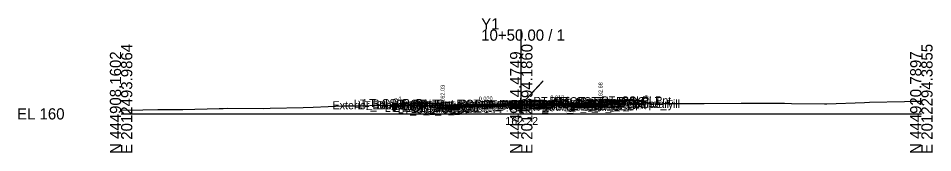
# Model space of a CAD drawing. Extents: x -26 to 3203, y -10 to 9517.
# Drawn here: x -25.7 to 202.8, y 990.3 to 1023.9 of the extents above; entities that cross this region are included whole.
import ezdxf

# ---------------------------------------------------------------- set-up
doc = ezdxf.new("R2010")
doc.units = 0
for name, color, linetype in [('Default', 7, 'Continuous'), ('Exist CMT Pavement', 7, 'Continuous'), ('Exist Cross Section Cell', 7, 'Continuous'), ('Exist XS Center Line Elevation Label', 7, 'Continuous'), ('Exist XS Ground Line', 7, 'Continuous'), ('Prop CMT Conc Surface', 7, 'Continuous'), ('Prop CMT Concrete Structures', 7, 'Continuous'), ('Prop CMT Pvmt Course 1', 7, 'Continuous'), ('Prop CMT Pvmt Course 1 CG', 7, 'Continuous'), ('Prop CMT Pvmt Course 1 Wedge', 7, 'Continuous'), ('Prop CMT Pvmt Course 2', 7, 'Continuous'), ('Prop CMT Pvmt Course 2 Wedge', 7, 'Continuous'), ('Prop CMT Pvmt Course 3', 7, 'Continuous'), ('Prop CMT Pvmt Course 3 Wedge', 7, 'Continuous'), ('Prop CMT Pvmt Surface', 7, 'Continuous'), ('Prop CMT Pvmt Wedge Surface 1', 7, 'Continuous'), ('Prop CMT Pvmt Wedge Surface 2', 7, 'Continuous'), ('Prop CMT Pvmt Wedge Surface 3', 7, 'Continuous'), ('Prop CMT Slope Grass', 7, 'Continuous'), ('Prop CMT Subgrade Earthwork', 7, 'Continuous'), ('Prop XS Earthwork Shape', 7, 'Continuous'), ('Prop XS Hydro Elevations', 7, 'Continuous'), ('Prop XS SE Text', 7, 'Continuous'), ('Prop XS Side Slope Text', 7, 'Continuous'), ('Prop XS Wedging', 7, 'Continuous'), ('Scratch_Level_0', 7, 'Continuous')]:
    doc.layers.add(name, color=color, linetype=linetype)

msp = doc.modelspace()

# ---------------------------------------------------------------- linework, layer by layer
at = {"layer": 'Exist CMT Pavement'}
for points in [[(100, 1002.22), (98.21, 1002.22), (86.33, 1001.92), (84.56, 1002.08)], [(100, 1002.22), (110.58, 1002.2), (112.49, 1002.51)]]:
    msp.add_lwpolyline(points, dxfattribs=at)
at = {"layer": 'Exist Cross Section Cell'}
for p, q in [((100, 1000), (100, 1021.08)), ((0, 1000), (100, 1000)), ((100, 1000), (200, 1000))]:
    msp.add_line(p, q, dxfattribs=at)
at = {"layer": 'Exist XS Ground Line'}
msp.add_lwpolyline([(0, 1000.89), (5.43, 1001.04), (9.2, 1001.07), (15.45, 1001.12), (24.5, 1001.38), (25.47, 1001.38), (26.57, 1001.42), (35.49, 1001.36), (37.27, 1001.4), (45.51, 1001.6), (47.97, 1001.69), (55.54, 1002), (58.67, 1002.05), (65.56, 1002.17), (75.21, 1002.13), (84.56, 1002.08), (86.33, 1001.92), (89.99, 1002.01), (98.21, 1002.22), (100, 1002.22), (103.35, 1002.21), (110.58, 1002.2), (112.07, 1002.45), (112.49, 1002.51), (118.65, 1002.5), (125.68, 1002.59), (133.55, 1002.48), (135.71, 1002.57), (144.25, 1002.63), (145.73, 1002.61), (154.95, 1002.72), (155.75, 1002.72), (165.77, 1002.66), (167.57, 1002.62), (175.79, 1002.52), (176.35, 1002.52), (185.81, 1002.87), (187.04, 1002.9), (195.83, 1003.07), (197.74, 1003.16), (200, 1003.18)], dxfattribs=at)
at = {"layer": 'Prop CMT Conc Surface'}
for points in [[(80.36, 1002.03), (80.36, 1002.53), (79.86, 1002.53)], [(82.36, 1002.15), (80.36, 1002.03)], [(117.82, 1002.74), (119.82, 1002.68)], [(119.82, 1002.68), (119.82, 1003.18), (120.32, 1003.18)]]:
    msp.add_lwpolyline(points, dxfattribs=at)
at = {"layer": 'Prop CMT Concrete Structures'}
for points in [[(82.36, 1002.15), (80.36, 1002.03), (80.36, 1002.53), (79.86, 1002.53)], [(79.86, 1002.53), (79.86, 1001.51), (82.36, 1001.56)], [(82.36, 1001.56), (82.36, 1002.15)], [(117.82, 1002.74), (119.82, 1002.68), (119.82, 1003.18), (120.32, 1003.18)], [(120.32, 1003.18), (120.32, 1002.19), (117.82, 1002.15)], [(117.82, 1002.15), (117.82, 1002.74)]]:
    msp.add_lwpolyline(points, dxfattribs=at)
at = {"layer": 'Prop CMT Pvmt Course 1'}
for points in [[(100, 1002.5), (82.36, 1002.15)], [(82.36, 1002.15), (82.36, 1001.9)], [(82.36, 1001.9), (84.56, 1001.94)], [(84.56, 1002.06), (100, 1002.37)], [(84.56, 1001.94), (84.56, 1002.06)], [(100, 1002.5), (117.82, 1002.74)], [(112.49, 1002.54), (100, 1002.37)], [(100, 1002.25), (100, 1002.5)], [(100, 1002.25), (100, 1002.5)], [(100, 1002.37), (100, 1002.25), (100, 1002.25)], [(100, 1002.37), (100, 1002.25), (100, 1002.25)], [(112.49, 1002.41), (112.49, 1002.54)], [(117.82, 1002.49), (112.49, 1002.41)], [(117.82, 1002.74), (117.82, 1002.49)]]:
    msp.add_lwpolyline(points, dxfattribs=at)
at = {"layer": 'Prop CMT Pvmt Course 1 CG'}
for points in [[(82.36, 1001.56), (79.36, 1001.5), (79.02, 1001.16)], [(79.02, 1001.16), (82.36, 1001.23)], [(82.36, 1001.23), (82.36, 1001.56)], [(117.82, 1002.15), (120.82, 1002.19), (121.15, 1001.86)], [(117.82, 1001.82), (117.82, 1002.15)], [(121.15, 1001.86), (117.82, 1001.82)]]:
    msp.add_lwpolyline(points, dxfattribs=at)
at = {"layer": 'Prop CMT Pvmt Course 1 Wedge'}
for points in [[(100, 1002.37), (84.56, 1002.06)], [(100, 1002.37), (112.49, 1002.54)]]:
    msp.add_lwpolyline(points, dxfattribs=at)
at = {"layer": 'Prop CMT Pvmt Course 2'}
for points in [[(84.56, 1001.94), (82.36, 1001.9)], [(82.36, 1001.9), (82.36, 1001.56)], [(82.36, 1001.56), (84.56, 1001.61)], [(84.56, 1001.61), (84.56, 1001.94)], [(112.49, 1002.41), (117.82, 1002.49)], [(112.49, 1002.08), (112.49, 1002.41)], [(117.82, 1002.15), (112.49, 1002.08)], [(117.82, 1002.49), (117.82, 1002.15)]]:
    msp.add_lwpolyline(points, dxfattribs=at)
at = {"layer": 'Prop CMT Pvmt Course 2 Wedge'}
for points in [[(100, 1002.25), (84.56, 1001.94)], [(100, 1002.25), (112.49, 1002.41)]]:
    msp.add_lwpolyline(points, dxfattribs=at)
at = {"layer": 'Prop CMT Pvmt Course 3'}
for points in [[(84.56, 1001.61), (82.36, 1001.56)], [(82.36, 1001.56), (82.36, 1001.23)], [(82.36, 1001.23), (84.56, 1001.27)], [(84.56, 1001.27), (84.56, 1001.61)], [(112.49, 1002.08), (117.82, 1002.15)], [(112.49, 1001.75), (112.49, 1002.08)], [(117.82, 1001.82), (112.49, 1001.75)], [(117.82, 1002.15), (117.82, 1001.82)]]:
    msp.add_lwpolyline(points, dxfattribs=at)
at = {"layer": 'Prop CMT Pvmt Course 3 Wedge'}
for points in [[(100, 1001.91), (84.56, 1001.61)], [(100, 1001.91), (112.49, 1002.08)]]:
    msp.add_lwpolyline(points, dxfattribs=at)
at = {"layer": 'Prop CMT Pvmt Surface'}
for points in [[(100, 1002.5), (82.36, 1002.15)], [(100, 1002.5), (117.82, 1002.74)]]:
    msp.add_lwpolyline(points, dxfattribs=at)
at = {"layer": 'Prop CMT Pvmt Wedge Surface 1'}
for points in [[(82.36, 1001.9), (82.36, 1002.15)], [(84.56, 1001.94), (82.36, 1001.9)], [(100, 1002.37), (84.56, 1002.06)], [(84.56, 1002.06), (84.56, 1001.94)], [(100, 1002.37), (112.49, 1002.54)], [(112.49, 1002.54), (112.49, 1002.41)], [(112.49, 1002.41), (117.82, 1002.49)], [(117.82, 1002.49), (117.82, 1002.74)]]:
    msp.add_lwpolyline(points, dxfattribs=at)
at = {"layer": 'Prop CMT Pvmt Wedge Surface 2'}
for points in [[(100, 1002.25), (82.36, 1001.9)], [(82.36, 1001.9), (82.36, 1002.15)], [(100, 1002.25), (117.82, 1002.49)], [(117.82, 1002.49), (117.82, 1002.74)]]:
    msp.add_lwpolyline(points, dxfattribs=at)
at = {"layer": 'Prop CMT Pvmt Wedge Surface 3'}
for points in [[(82.36, 1001.56), (82.36, 1002.15)], [(100, 1001.91), (82.36, 1001.56)], [(100, 1001.91), (117.82, 1002.15)], [(117.82, 1002.15), (117.82, 1002.74)]]:
    msp.add_lwpolyline(points, dxfattribs=at)
at = {"layer": 'Prop CMT Slope Grass'}
for points in [[(120.32, 1003.18), (129.82, 1003.37), (132.45, 1002.5)], [(79.86, 1002.53), (70.36, 1002.72), (68.69, 1002.16)]]:
    msp.add_lwpolyline(points, dxfattribs=at)
at = {"layer": 'Prop CMT Subgrade Earthwork'}
for points in [[(82.36, 1001.23), (79.02, 1001.16), (77.61, 1002.57)], [(84.56, 1001.27), (82.36, 1001.23)], [(84.56, 1001.27), (84.57, 1002.08)], [(112.49, 1001.75), (112.48, 1002.51)], [(112.49, 1001.75), (117.82, 1001.82)], [(117.82, 1001.82), (121.15, 1001.86), (122.51, 1003.23)]]:
    msp.add_lwpolyline(points, dxfattribs=at)
at = {"layer": 'Prop XS Earthwork Shape'}
for points in [[(121.83, 1002.54), (125.68, 1002.59), (132.45, 1002.5), (129.82, 1003.37), (122.51, 1003.23)], [(78.07, 1002.12), (77.61, 1002.57), (70.36, 1002.72), (68.69, 1002.16), (75.21, 1002.13)], [(78.07, 1002.12), (79.86, 1002.11), (79.86, 1001.51), (82.36, 1001.56), (82.36, 1002.09), (84.56, 1002.08), (84.57, 1002.08), (84.56, 1001.27), (82.36, 1001.23), (79.02, 1001.16)], [(81.56, 1002.1), (80.36, 1002.03), (80.36, 1002.1), (79.86, 1002.11), (79.86, 1001.51), (82.36, 1001.56), (82.36, 1002.09)], [(81.56, 1002.1), (80.36, 1002.03), (80.36, 1002.1)], [(100, 1002.22), (103.35, 1002.21), (110.58, 1002.2)], [(112.07, 1002.45), (112.48, 1002.51), (110.58, 1002.2)], [(112.48, 1002.51), (112.49, 1002.51), (117.82, 1002.51), (117.82, 1002.15), (120.32, 1002.19), (120.32, 1002.53), (121.83, 1002.54), (121.15, 1001.86), (117.82, 1001.82), (112.49, 1001.75)], [(117.82, 1002.51), (118.65, 1002.5), (120.32, 1002.53), (120.32, 1002.19), (117.82, 1002.15)]]:
    msp.add_lwpolyline(points, close=True, dxfattribs=at)
at = {"layer": 'Prop XS Wedging'}
for p, q in [((100, 1002.37), (105.51, 1008.29)), ((100, 1002.37), (105.23, 1007.95)), ((100, 1002.37), (84.71, 1002.07)), ((84.71, 1002.07), (85.83, 1001.96)), ((97.26, 1002.19), (85.83, 1001.96)), ((85.83, 1001.96), (97.26, 1002.19)), ((85.83, 1001.96), (86.33, 1001.92)), ((97.26, 1002.19), (98.21, 1002.22)), ((98.21, 1002.22), (98.45, 1002.22)), ((98.45, 1002.22), (100, 1002.25)), ((100, 1002.25), (98.45, 1002.22)), ((98.45, 1002.22), (100, 1002.22)), ((112.49, 1002.54), (100, 1002.37)), ((111.81, 1002.41), (100, 1002.25)), ((100, 1002.25), (111.81, 1002.41)), ((100, 1002.37), (100, 1002.25)), ((100, 1002.25), (100, 1002.37)), ((100, 1002.25), (100, 1002.22)), ((100, 1002.22), (100, 1002.25)), ((100, 1002.22), (103.35, 1002.21)), ((112.48, 1002.51), (112.48, 1002.51)), ((112.48, 1002.51), (112.49, 1002.51)), ((112.49, 1002.51), (112.49, 1002.54)), ((112.49, 1002.51), (112.49, 1002.51))]:
    msp.add_line(p, q, dxfattribs=at)
for points in [[(86.33, 1001.92), (89.99, 1002.01), (97.26, 1002.19)], [(103.35, 1002.21), (110.58, 1002.2), (111.81, 1002.41)], [(111.81, 1002.41), (112.07, 1002.45), (112.48, 1002.51)], [(112.48, 1002.51), (112.48, 1002.51)]]:
    msp.add_lwpolyline(points, dxfattribs=at)

# ---------------------------------------------------------------- texts
at = {"layer": 'Default'}
msp.add_text('-', height=0.0001, dxfattribs=at).set_placement((0, 1000))
at = {"layer": 'Exist Cross Section Cell'}
for s, p in [('Y1', (90, 1021.08)), ('10+50.00 / 1', (90, 1018.28)), ('EL 160', (-26, 998.6))]:
    msp.add_text(s, height=2.8, dxfattribs=at).set_placement(p)
for s, p in [('E 2012493.9864', (2.8, 990)), ('E 2012394.1860', (102.8, 990)), ('E 2012294.3855', (202.8, 990)), ('N 444908.1602', (0, 990)), ('N 444914.4749', (100, 990)), ('N 444920.7897', (200, 990))]:
    msp.add_text(s, height=2.8, rotation=90, dxfattribs=at).set_placement(p)
at = {"layer": 'Exist XS Center Line Elevation Label'}
msp.add_text('162.22', height=2, dxfattribs=at).set_placement((96.03, 997.22))
at = {"layer": 'Prop XS Hydro Elevations'}
for s, p in [('162.03', (80.86, 1003.03)), ('162.68', (120.32, 1003.68))]:
    msp.add_text(s, height=1, rotation=90, dxfattribs=at).set_placement(p)
at = {"layer": 'Prop XS SE Text'}
for s, rotation, p in [('0.020', 1.1458, (89.41, 1003.29)), ('0.013', 0.7639, (107.29, 1003.6))]:
    msp.add_text(s, height=1, rotation=rotation, dxfattribs=at).set_placement(p)
at = {"layer": 'Prop XS Side Slope Text'}
for rotation, p in [(18.4332, (68.54, 1002.9)), (341.5668, (130.62, 1003.9))]:
    msp.add_text('3:1', height=1, rotation=rotation, dxfattribs=at).set_placement(p)
at = {"layer": 'Scratch_Level_0'}
for s, p in [('Exterior Boundary', (52.84, 1001.16)), ('LT_Sub_Trench_Out_DLT', (58.18, 1001.57)), ('LT_Slope_Fill', (59.21, 1001.16)), ('LT_CSLP_Pnt', (60.53, 1001.72)), ('LT_CG_Top_Face', (67.62, 1001.53)), ('LT_CG_Top_BOC', (68.14, 1001.53)), ('RT_PV2_IEEOP', (89.91, 1001.25)), ('LT_PV2_IEEOP', (89.95, 1001.25)), ('RT_PV1_IEEOP', (90.47, 1001.37)), ('LT_PV1_IEEOP', (90.52, 1001.37)), ('PV2_PGL', (93.91, 1001.25)), ('PV1_PGL', (94.47, 1001.5)), ('RT_PV_Sub_Tie_Out', (97.37, 1001.51)), ('RT_PV_OEEOP_EG', (99.99, 1001.51)), ('RT_PV2_OEEOP', (101.75, 1001.41)), ('RT_PV1_OEEOP', (102.32, 1001.54)), ('RT_Sub_Trench_Out_DLT', (103.03, 1002.23)), ('RT_CG_Top_Face', (107.03, 1002.18)), ('RT_CG1_Shelf_Out', (107.32, 1001.19)), ('RT_PV2_OEOT', (107.94, 1001.49)), ('RT_CG_Top_Gut', (108.01, 1001.68)), ('RT_PV1_OEOT', (108.51, 1001.74)), ('RT_CG_Top_BOC', (108.56, 1002.18)), ('Exterior Boundary', (116.59, 1001.5)), ('RT_CSLP_Pnt', (119.95, 1002.37)), ('RT_Slope_Fill', (122.92, 1001.5)), ('LT_CG1_Shelf_Out', (65.91, 1000.5)), ('LT_CG_Bot_BOC', (68.17, 1000.51)), ('LT_CG_Top_Gut', (68.6, 1001.03)), ('LT_Sub_OEOP', (69.13, 1000.16)), ('LT_PV_Sub_Tie_Out', (69.52, 1001.08)), ('LT_PV_OEEOP_EG', (72.1, 1001.08)), ('LT_CG_Bot_IE', (72.27, 1000.56)), ('LT_Sub_OEOT', (72.44, 1000.23)), ('LT_PV2_OEOT', (72.53, 1000.9)), ('LT_PV3_OEOT', (72.53, 1000.56)), ('LT_PV1_OEOT', (73.1, 1001.15)), ('LT_Sub_OEEOP', (73.77, 1000.27)), ('LT_PV2_OEEOP', (73.87, 1000.94)), ('LT_PV3_OEEOP', (73.87, 1000.61)), ('LT_PV1_OEEOP', (74.43, 1001.06)), ('RT_PV_IEEOP_EG', (88.14, 1001.22)), ('LT_PV_IEEOP_EG', (88.19, 1001.22)), ('RT_PV3_IEEOP', (89.91, 1000.91)), ('LT_PV3_IEEOP', (89.95, 1000.91)), ('RT_Sub_OEEOP', (101.66, 1000.75)), ('RT_PV3_OEEOP', (101.75, 1001.08)), ('RT_CG_Bot_IE', (107.68, 1001.15)), ('RT_Sub_OEOT', (107.85, 1000.82)), ('RT_PV3_OEOT', (107.94, 1001.15)), ('RT_CG_Bot_BOC', (108.59, 1001.19)), ('RT_Sub_OEOP', (111.21, 1000.86))]:
    msp.add_text(s, height=2, dxfattribs=at).set_placement(p)

doc.saveas('drawing.dxf')
